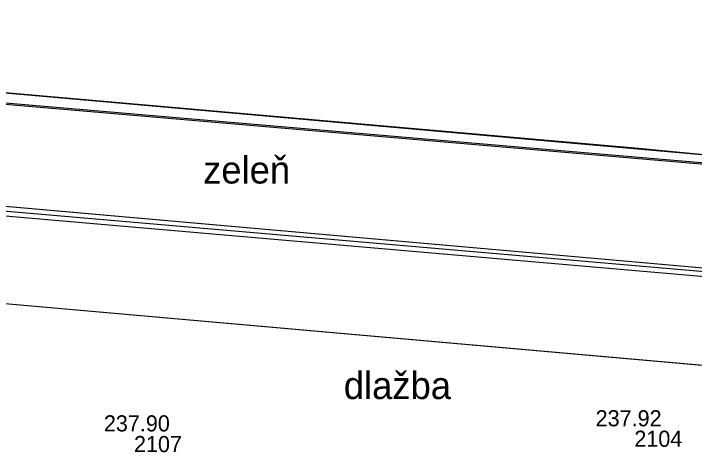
# Model space of a CAD drawing. Extents: x -264205 to -263659, y -1242401 to -1241986.
# Drawn here: x -263886.34 to -263865.23, y -1242074.23 to -1242060.64 of the extents above; entities that cross this region are included whole.
import ezdxf

# ---------------------------------------------------------------- set-up
doc = ezdxf.new("R2010")
doc.units = 0
for name, color, linetype in [('BOD_CISLO_2-2', 7, 'Continuous'), ('BOD_VYSKA_2-2', 7, 'Continuous'), ('POPIS_2-2', 7, 'Continuous'), ('PROJEKT_OBRUBNIKY_KOMUNIKACIE', 7, 'Continuous'), ('SITUACIA_DSP_2D', 7, 'Continuous'), ('SO_20-4_OBRUBNIKY_DOLNA_HRANA', 7, 'Continuous'), ('SO_20-4_OBRUBNIKY_HORNA_HRANA', 7, 'Continuous')]:
    doc.layers.add(name, color=color, linetype=linetype)

msp = doc.modelspace()

# ---------------------------------------------------------------- linework, layer by layer
at = {"layer": 'PROJEKT_OBRUBNIKY_KOMUNIKACIE'}
msp.add_line((-263866.963, -1242064.823), (-263895.455, -1242062.322), dxfattribs=at)
for points in [[(-263863.949, -1242065.106), (-263895.455, -1242062.322), (-263915.197, -1242060.921), (-263926.771, -1242063.254), (-263950.745, -1242062.149), (-263959.468, -1242059.534)], [(-263864.257, -1242068.593), (-263895.733, -1242065.811), (-263914.971, -1242064.445), (-263926.501, -1242066.77), (-263951.337, -1242065.625), (-263959.611, -1242063.145)], [(-263864.521, -1242071.581), (-263895.971, -1242068.802), (-263914.777, -1242067.467), (-263926.271, -1242069.784), (-263951.845, -1242068.605), (-263959.611, -1242066.277)]]:
    msp.add_lwpolyline(points, dxfattribs=at)
at = {"layer": 'SITUACIA_DSP_2D'}
for p, q in [((-263866.964, -1242064.823), (-263895.455, -1242062.322)), ((-263863.949, -1242065.106), (-263895.455, -1242062.322)), ((-263816.79, -1242069.539), (-263866.964, -1242064.823)), ((-263864.257, -1242068.593), (-263895.733, -1242065.811)), ((-263864.521, -1242071.581), (-263895.971, -1242068.802))]:
    msp.add_line(p, q, dxfattribs=at)
at = {"layer": 'SO_20-4_OBRUBNIKY_DOLNA_HRANA'}
msp.add_lwpolyline([(-263926.563, -1242066.793), (-263914.806, -1242064.459), (-263888.634, -1242066.727), (-263862.406, -1242069), (-263841.103, -1242070.841)], dxfattribs=at)
at = {"layer": 'SO_20-4_OBRUBNIKY_HORNA_HRANA'}
for points in [[(-263925.759, -1242063.066), (-263915.181, -1242060.928), (-263888.287, -1242063.258), (-263862.248, -1242065.492), (-263835.778, -1242067.791)], [(-263925.75, -1242063.112), (-263915.188, -1242060.971), (-263888.294, -1242063.301), (-263862.255, -1242065.535), (-263835.78, -1242067.841)], [(-263926.593, -1242066.647), (-263914.79, -1242064.308), (-263888.584, -1242066.589), (-263862.408, -1242068.845), (-263841.091, -1242070.689)]]:
    msp.add_lwpolyline(points, dxfattribs=at)

# ---------------------------------------------------------------- texts
at = {"layer": 'BOD_CISLO_2-2'}
for s, p in [('2107', (-263882.608, -1242074.226)), ('2104', (-263867.091, -1242074.061))]:
    msp.add_text(s, height=0.5, dxfattribs=at).set_placement(p)
at = {"layer": 'BOD_VYSKA_2-2'}
for s, p in [('237.90', (-263883.541, -1242073.585)), ('237.92', (-263868.291, -1242073.426))]:
    msp.add_text(s, height=0.5, dxfattribs=at).set_placement(p)
at = {"layer": 'POPIS_2-2'}
for s, p in [('zeleň', (-263880.463, -1242065.904)), ('dlažba', (-263876.101, -1242072.582))]:
    msp.add_text(s, height=0.8438, dxfattribs=at).set_placement(p)

doc.saveas('drawing.dxf')
